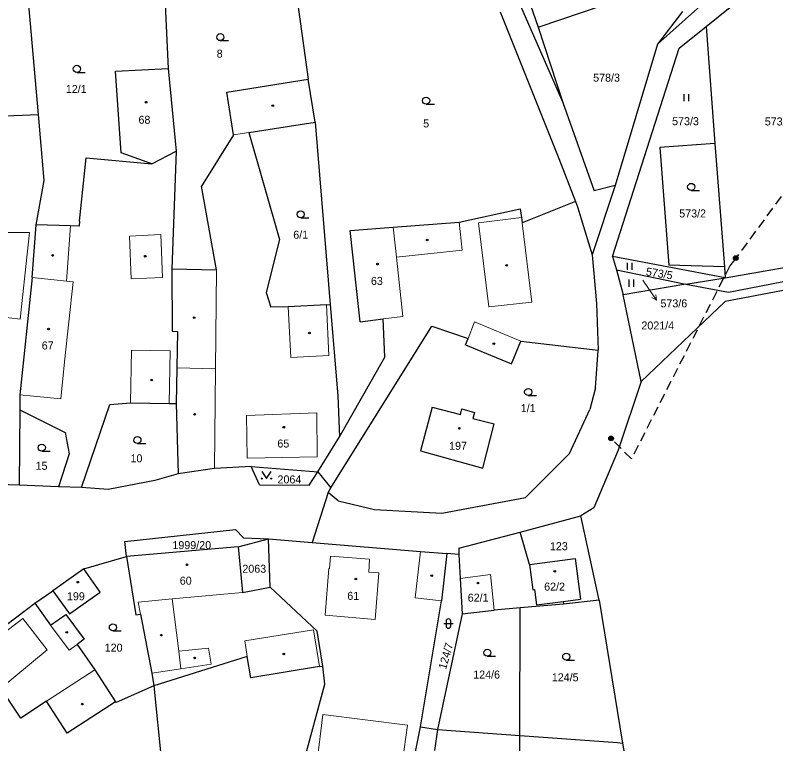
# Model space of a CAD drawing. Extents: x -820420 to -815896, y -1105820 to -1103643.
# Drawn here: x -817534.2 to -817372.7, y -1104713.1 to -1104558.3 of the extents above; entities that cross this region are included whole.
import ezdxf
from ezdxf.enums import TextEntityAlignment as Align

# ---------------------------------------------------------------- set-up
doc = ezdxf.new("R2010")
doc.units = 0
doc.header["$LTSCALE"] = 0.68
doc.linetypes.add('MEDIUM_DASHED', pattern=[4.5, 3, -1.5])
for name, color, linetype, lineweight in [('1', 7, 'Continuous', 25), ('3', 7, 'Continuous', 25), ('4', 7, 'Continuous', 13), ('5', 7, 'Continuous', 25), ('6', 7, 'Continuous', 25), ('7', 7, 'Continuous', 13)]:
    doc.layers.add(name, color=color, linetype=linetype, lineweight=lineweight)
doc.layers.add('2', color=7, linetype='Continuous')

msp = doc.modelspace()

# ---------------------------------------------------------------- linework, layer by layer
at = {"layer": '1'}
for p, q in [((-817441.18, -1104523.68), (-817417.92, -1104576.87)), ((-817502.73, -1104548.77), (-817501.77, -1104569.64)), ((-817475.12, -1104549.37), (-817472.04, -1104571.95)), ((-817423.18, -1104560.9), (-817391.37, -1104550.02)), ((-817529.32, -1104579.44), (-817531.74, -1104551.54)), ((-817426.48, -1104551.26), (-817423.18, -1104560.9)), ((-817397.84, -1104564.5), (-817382.77, -1104550.99)), ((-817387.52, -1104560.73), (-817379.33, -1104554.1)), ((-817431.25, -1104557.62), (-817418.76, -1104588.74)), ((-817392.52, -1104557.51), (-817397.84, -1104564.5)), ((-817423.18, -1104560.9), (-817417.92, -1104576.87)), ((-817393.24, -1104565.36), (-817387.52, -1104560.73)), ((-817387.52, -1104560.73), (-817385.62, -1104585.58)), ((-817397.84, -1104564.5), (-817406.82, -1104594.49)), ((-817407.42, -1104609.58), (-817393.24, -1104565.36)), ((-817512.93, -1104570.24), (-817501.77, -1104569.64)), ((-817501.77, -1104569.64), (-817500.07, -1104587.25)), ((-817511.77, -1104587.6), (-817512.93, -1104570.24)), ((-817489.29, -1104574.65), (-817472.04, -1104571.95)), ((-817470.51, -1104581.09), (-817472.04, -1104571.95)), ((-817487.91, -1104583.78), (-817489.29, -1104574.65)), ((-817417.92, -1104576.87), (-817411.31, -1104595.61)), ((-817549.95, -1104580.27), (-817529.32, -1104579.44)), ((-817528.1, -1104593.46), (-817529.32, -1104579.44)), ((-817484.66, -1104583.28), (-817470.51, -1104581.09)), ((-817470.51, -1104581.09), (-817467.34, -1104619.81)), ((-817487.91, -1104583.78), (-817494.65, -1104594.66)), ((-817484.66, -1104583.28), (-817478.11, -1104605.95)), ((-817385.62, -1104585.58), (-817397.32, -1104586.47)), ((-817385.62, -1104585.58), (-817383.62, -1104611.82)), ((-817505.24, -1104589.89), (-817511.77, -1104587.6)), ((-817505.24, -1104589.89), (-817500.07, -1104587.25)), ((-817500.07, -1104587.25), (-817500.99, -1104612.19)), ((-817397.32, -1104586.47), (-817395.42, -1104611.47)), ((-817520.58, -1104602.07), (-817519.18, -1104588.65)), ((-817519.18, -1104588.65), (-817505.24, -1104589.89)), ((-817418.76, -1104588.74), (-817415.22, -1104597.92)), ((-817529.8, -1104602.87), (-817528.1, -1104593.46)), ((-817491.49, -1104612.43), (-817494.65, -1104594.66)), ((-817406.82, -1104594.49), (-817411.74, -1104609.27)), ((-817406.82, -1104594.49), (-817411.31, -1104595.61)), ((-817415.22, -1104597.92), (-817426.54, -1104602.45)), ((-817415.22, -1104597.92), (-817414.8, -1104599.04)), ((-817414.8, -1104599.04), (-817411.74, -1104609.27)), ((-817439.94, -1104602.31), (-817426.97, -1104599.46)), ((-817426.97, -1104599.46), (-817426.69, -1104601.3)), ((-817520.58, -1104602.07), (-817520.69, -1104603.15)), ((-817453.96, -1104603.38), (-817439.94, -1104602.31)), ((-817426.69, -1104601.3), (-817426.54, -1104602.45)), ((-817530.64, -1104614.06), (-817529.8, -1104602.87)), ((-817522.52, -1104603.09), (-817529.8, -1104602.87)), ((-817520.69, -1104603.15), (-817522.52, -1104603.09)), ((-817463.07, -1104604.07), (-817453.96, -1104603.38)), ((-817461.01, -1104623.45), (-817463.07, -1104604.07)), ((-817478.11, -1104605.95), (-817480.92, -1104617.24)), ((-817383.44, -1104614.12), (-817352.01, -1104608.6)), ((-817411.74, -1104609.27), (-817410.77, -1104619.61)), ((-817383.44, -1104614.12), (-817407.42, -1104609.58)), ((-817383.62, -1104611.82), (-817395.42, -1104611.47)), ((-817383.62, -1104611.82), (-817383.44, -1104614.12)), ((-817382.75, -1104617.18), (-817351.68, -1104611.19)), ((-817500.99, -1104612.19), (-817500.9, -1104625.43)), ((-817500.99, -1104612.19), (-817491.49, -1104612.43)), ((-817406.55, -1104612.43), (-817391.79, -1104615.47)), ((-817351.25, -1104613.05), (-817383.47, -1104619.16)), ((-817530.64, -1104614.06), (-817533.25, -1104639.01)), ((-817391.79, -1104615.47), (-817383.44, -1104614.12)), ((-817391.79, -1104615.47), (-817405.13, -1104617.71)), ((-817391.79, -1104615.47), (-817382.75, -1104617.18)), ((-817480.92, -1104617.24), (-817479.98, -1104620.37)), ((-817401.27, -1104636.18), (-817405.13, -1104617.71)), ((-817468.15, -1104619.86), (-817476.24, -1104620.27)), ((-817468.15, -1104619.86), (-817467.34, -1104619.81)), ((-817467.34, -1104619.81), (-817465.75, -1104639.18)), ((-817410.77, -1104619.61), (-817410.43, -1104629.49)), ((-817383.47, -1104619.16), (-817401.27, -1104636.18)), ((-817476.24, -1104620.27), (-817479.98, -1104620.37)), ((-817461.01, -1104623.45), (-817456.08, -1104622.84)), ((-817455.74, -1104630.98), (-817456.08, -1104622.84)), ((-817467.19, -1104658.73), (-817445.78, -1104624.37)), ((-817445.78, -1104624.37), (-817438.05, -1104627.03)), ((-817500.9, -1104625.43), (-817499.77, -1104625.53)), ((-817499.77, -1104625.53), (-817499.91, -1104633.28)), ((-817438.58, -1104628.39), (-817438.05, -1104627.03)), ((-817428.81, -1104632.43), (-817426.85, -1104627.58)), ((-817426.85, -1104627.58), (-817410.43, -1104629.49)), ((-817438.58, -1104628.39), (-817428.81, -1104632.43)), ((-817411.02, -1104637.48), (-817410.43, -1104629.49)), ((-817465.4, -1104647.88), (-817455.74, -1104630.98)), ((-817499.91, -1104633.28), (-817500.05, -1104640.8)), ((-817401.27, -1104636.18), (-817406.17, -1104650.76)), ((-817411.02, -1104637.48), (-817412.18, -1104642.11)), ((-817533.25, -1104639.01), (-817533.28, -1104642.16)), ((-817465.75, -1104639.18), (-817465.4, -1104647.88)), ((-817520.18, -1104658.67), (-817514.17, -1104641.02)), ((-817514.17, -1104641.02), (-817509.75, -1104640.7)), ((-817509.75, -1104640.7), (-817501.55, -1104640.81)), ((-817501.55, -1104640.81), (-817500.05, -1104640.8)), ((-817500.05, -1104640.8), (-817499.62, -1104655.74)), ((-817533.28, -1104642.16), (-817533.4, -1104658.16)), ((-817533.28, -1104642.16), (-817523.63, -1104646.99)), ((-817445.68, -1104641.62), (-817448.13, -1104650.89)), ((-817445.68, -1104641.62), (-817439.69, -1104643.2)), ((-817439.69, -1104643.2), (-817439.36, -1104641.94)), ((-817439.36, -1104641.94), (-817436.73, -1104642.75)), ((-817436.73, -1104642.75), (-817437.05, -1104644.03)), ((-817416.53, -1104651.45), (-817412.18, -1104642.11)), ((-817437.05, -1104644.03), (-817432.54, -1104645.18)), ((-817434.95, -1104654.6), (-817432.54, -1104645.18)), ((-817523.63, -1104646.99), (-817522.78, -1104651.49)), ((-817469.96, -1104655.35), (-817465.4, -1104647.88)), ((-817448.13, -1104650.89), (-817434.95, -1104654.6)), ((-817406.17, -1104650.76), (-817411.32, -1104662.96)), ((-817522.78, -1104651.49), (-817525.03, -1104658.56)), ((-817425.83, -1104660.79), (-817416.53, -1104651.45)), ((-817499.62, -1104655.74), (-817504.59, -1104657.17)), ((-817491.9, -1104654.63), (-817499.62, -1104655.74)), ((-817484.15, -1104654.2), (-817491.9, -1104654.63)), ((-817484.15, -1104654.2), (-817469.96, -1104655.35)), ((-817482.35, -1104658.14), (-817484.15, -1104654.2)), ((-817471.82, -1104658.18), (-817469.96, -1104655.35)), ((-817469.96, -1104655.35), (-817467.19, -1104658.73)), ((-817504.59, -1104657.17), (-817514.48, -1104659.13)), ((-817533.4, -1104658.16), (-817540.36, -1104657.93)), ((-817525.03, -1104658.56), (-817533.4, -1104658.16)), ((-817520.18, -1104658.67), (-817525.03, -1104658.56)), ((-817514.48, -1104659.13), (-817520.18, -1104658.67)), ((-817482.35, -1104658.14), (-817471.82, -1104658.18)), ((-817467.8, -1104659.72), (-817467.19, -1104658.73)), ((-817467.8, -1104659.72), (-817471.18, -1104670.36)), ((-817465.66, -1104661.53), (-817467.8, -1104659.72)), ((-817465.66, -1104661.53), (-817457.93, -1104663.36)), ((-817443.6, -1104664.13), (-817425.83, -1104660.79)), ((-817457.93, -1104663.36), (-817443.6, -1104664.13)), ((-817411.32, -1104662.96), (-817414.13, -1104664.73)), ((-817426.97, -1104668.14), (-817414.13, -1104664.73)), ((-817410.25, -1104682.64), (-817414.13, -1104664.73)), ((-817510.93, -1104670.14), (-817487.47, -1104667.61)), ((-817487.47, -1104667.61), (-817485.77, -1104669.36)), ((-817440.04, -1104671.55), (-817426.97, -1104668.14)), ((-817425.03, -1104675.01), (-817426.97, -1104668.14)), ((-817510.59, -1104673.34), (-817510.93, -1104670.14)), ((-817486.89, -1104671.29), (-817480.45, -1104669.56)), ((-817485.77, -1104669.36), (-817480.45, -1104669.56)), ((-817480.06, -1104679.83), (-817480.45, -1104669.56)), ((-817480.45, -1104669.56), (-817471.18, -1104670.36)), ((-817486.89, -1104671.29), (-817510.59, -1104673.34)), ((-817486.89, -1104671.29), (-817486.27, -1104677.91)), ((-817471.18, -1104670.36), (-817448.16, -1104672.27)), ((-817440.04, -1104671.55), (-817439.99, -1104672.94)), ((-817519.66, -1104675.99), (-817510.59, -1104673.34)), ((-817510.59, -1104673.34), (-817508.6, -1104685.74)), ((-817448.16, -1104672.27), (-817442.59, -1104672.69)), ((-817442.59, -1104672.69), (-817443.7, -1104682.77)), ((-817439.99, -1104672.94), (-817442.59, -1104672.69)), ((-817439.99, -1104672.94), (-817439.74, -1104678.02)), ((-817425.03, -1104675.01), (-817415.32, -1104673.77)), ((-817425.03, -1104675.01), (-817424.33, -1104680.42)), ((-817415.32, -1104673.77), (-817414.21, -1104682.42)), ((-817519.66, -1104675.99), (-817526.22, -1104680.64)), ((-817516.18, -1104680.91), (-817519.66, -1104675.99)), ((-817486.27, -1104677.91), (-817485.99, -1104680.95)), ((-817439.74, -1104678.02), (-817439.3, -1104685.53)), ((-817485.99, -1104680.95), (-817480.06, -1104679.83)), ((-817480.06, -1104679.83), (-817470.1, -1104689.17)), ((-817530.1, -1104683.23), (-817526.22, -1104680.64)), ((-817526.22, -1104680.64), (-817522.72, -1104685.55)), ((-817522.72, -1104685.55), (-817516.18, -1104680.91)), ((-817424.33, -1104680.42), (-817423.93, -1104680.37)), ((-817423.93, -1104680.37), (-817423.51, -1104683.62)), ((-817448.17, -1104709.55), (-817443.7, -1104682.77)), ((-817423.51, -1104683.62), (-817417.86, -1104682.89)), ((-817417.86, -1104682.89), (-817414.21, -1104682.42)), ((-817417.86, -1104682.89), (-817417.8, -1104683.46)), ((-817410.25, -1104682.64), (-817417.8, -1104683.46)), ((-817410.25, -1104682.64), (-817405.25, -1104712.96)), ((-817538.53, -1104689.62), (-817530.1, -1104683.23)), ((-817530.1, -1104683.23), (-817526.76, -1104687.93)), ((-817439.3, -1104685.53), (-817432.5, -1104684.76)), ((-817426.99, -1104684.27), (-817432.5, -1104684.76)), ((-817427.05, -1104711.34), (-817426.99, -1104684.27)), ((-817417.8, -1104683.46), (-817426.99, -1104684.27)), ((-817526.76, -1104687.93), (-817523.51, -1104685.66)), ((-817523.51, -1104685.66), (-817519.58, -1104690.88)), ((-817508.6, -1104685.74), (-817507.66, -1104685.6)), ((-817507.66, -1104685.6), (-817505.24, -1104698.12)), ((-817439.3, -1104685.53), (-817444.53, -1104710.06)), ((-817468.92, -1104696.62), (-817470.1, -1104689.17)), ((-817519.58, -1104690.88), (-817521.08, -1104692.02)), ((-817521.08, -1104692.02), (-817517.33, -1104697.42)), ((-817484.96, -1104694.6), (-817504.8, -1104700.81)), ((-817484.22, -1104699.11), (-817484.96, -1104694.6)), ((-817517.33, -1104697.42), (-817512.91, -1104704.21)), ((-817469.61, -1104696.73), (-817484.22, -1104699.11)), ((-817469.61, -1104696.73), (-817468.92, -1104696.62)), ((-817468.5, -1104700.47), (-817468.92, -1104696.62)), ((-817505.24, -1104698.12), (-817504.8, -1104700.81)), ((-817504.8, -1104700.81), (-817512.8, -1104704.38)), ((-817504.8, -1104700.81), (-817500.74, -1104740.44)), ((-817472.89, -1104716.68), (-817468.5, -1104700.47)), ((-817533.07, -1104707.69), (-817536.14, -1104703)), ((-817527.59, -1104704.1), (-817533.07, -1104707.69)), ((-817523.18, -1104710.89), (-817527.59, -1104704.1)), ((-817512.91, -1104704.21), (-817523.18, -1104710.89)), ((-817512.91, -1104704.21), (-817512.8, -1104704.38)), ((-817450.14, -1104719.46), (-817448.17, -1104709.55)), ((-817448.17, -1104709.55), (-817444.53, -1104710.06)), ((-817444.53, -1104710.06), (-817445.18, -1104714.52)), ((-817444.53, -1104710.06), (-817427.05, -1104711.34)), ((-817427.12, -1104719.23), (-817427.05, -1104711.34)), ((-817427.05, -1104711.34), (-817406.31, -1104712.85)), ((-817406.31, -1104712.85), (-817405.25, -1104712.96)), ((-817405.25, -1104712.96), (-817404.87, -1104715.4))]:
    msp.add_line(p, q, dxfattribs=at)
msp.add_lwpolyline([(-817407.42, -1104609.58), (-817406.55, -1104612.43), (-817405.13, -1104617.71)], dxfattribs=at)
at = {"layer": '3'}
for p, q in [((-817490.693, -1104563.73), (-817488.943, -1104563.73)), ((-817521.153, -1104570.48), (-817519.403, -1104570.48)), ((-817392.191, -1104576.6), (-817392.191, -1104575.1)), ((-817391.19, -1104576.6), (-817391.19, -1104575.1)), ((-817446.963, -1104577.23), (-817445.213, -1104577.23)), ((-817390.673, -1104595.56), (-817388.923, -1104595.56)), ((-817473.613, -1104601.39), (-817471.863, -1104601.39)), ((-817404.211, -1104612.41), (-817404.211, -1104610.91)), ((-817403.21, -1104612.41), (-817403.21, -1104610.91)), ((-817403.881, -1104616.01), (-817403.881, -1104614.51)), ((-817402.88, -1104616.01), (-817402.88, -1104614.51)), ((-817425.293, -1104639.14), (-817423.543, -1104639.14)), ((-817508.283, -1104649.35), (-817506.533, -1104649.35)), ((-817528.593, -1104650.96), (-817526.843, -1104650.96)), ((-817443.221, -1104687.591), (-817441.219, -1104687.591)), ((-817442.721, -1104687.091), (-817442.721, -1104688.092)), ((-817441.719, -1104688.092), (-817441.719, -1104687.091)), ((-817513.503, -1104689.14), (-817511.753, -1104689.14)), ((-817433.983, -1104694.53), (-817432.233, -1104694.53)), ((-817417.213, -1104695.36), (-817415.463, -1104695.36))]:
    msp.add_line(p, q, dxfattribs=at)
msp.add_lwpolyline([(-817481.89, -1104655.269), (-817480.89, -1104656.77), (-817479.89, -1104655.269)], dxfattribs=at)
for centre, radius in [((-817490.6929, -1104562.9798), 0.75), ((-817521.1529, -1104569.7298), 0.75), ((-817446.9629, -1104576.4798), 0.75), ((-817390.6729, -1104594.8098), 0.75), ((-817473.6129, -1104600.6398), 0.75), ((-817425.2929, -1104638.3898), 0.75), ((-817508.2829, -1104648.5998), 0.75), ((-817528.5929, -1104650.2098), 0.75), ((-817481.89, -1104656.7695), 0.1), ((-817479.89, -1104656.7695), 0.1), ((-817513.5029, -1104688.3898), 0.75), ((-817433.9829, -1104693.7798), 0.75), ((-817417.2129, -1104694.6098), 0.75)]:
    msp.add_circle(centre, radius, dxfattribs=at)
for centre, start, end in [((-817442.22, -1104687.0909), 0, 180), ((-817442.22, -1104688.0909), 180, 359.98789)]:
    msp.add_arc(centre, 0.5, start, end, dxfattribs=at)
at = {"layer": '4'}
for p, q in [((-817487.91, -1104583.78), (-817484.66, -1104583.28)), ((-817439.29, -1104608.24), (-817439.94, -1104602.31)), ((-817435.83, -1104602.42), (-817426.69, -1104601.3)), ((-817433.65, -1104620.26), (-817435.83, -1104602.42)), ((-817523.37, -1104614.82), (-817522.52, -1104603.09)), ((-817453.26, -1104609.76), (-817453.96, -1104603.38)), ((-817426.54, -1104602.45), (-817424.49, -1104619.29)), ((-817538.57, -1104604.48), (-817531.2, -1104604.49)), ((-817531.2, -1104604.49), (-817533.18, -1104622.89)), ((-817503.3, -1104604.95), (-817509.94, -1104605.25)), ((-817509.94, -1104605.25), (-817509.6, -1104614.32)), ((-817502.96, -1104614.07), (-817503.3, -1104604.95)), ((-817453.26, -1104609.76), (-817439.29, -1104608.24)), ((-817451.89, -1104622.34), (-817453.26, -1104609.76)), ((-817523.37, -1104614.82), (-817530.64, -1104614.06)), ((-817523.79, -1104632), (-817521.93, -1104614.97)), ((-817521.93, -1104614.97), (-817523.37, -1104614.82)), ((-817509.6, -1104614.32), (-817502.96, -1104614.07)), ((-817468.15, -1104619.86), (-817467.61, -1104630.62)), ((-817424.49, -1104619.29), (-817433.65, -1104620.26)), ((-817475.7, -1104631.03), (-817476.24, -1104620.27)), ((-817540.5, -1104622.09), (-817533.18, -1104622.89)), ((-817456.08, -1104622.84), (-817451.89, -1104622.34)), ((-817436.7, -1104623.51), (-817438.05, -1104627.03)), ((-817436.7, -1104623.51), (-817426.85, -1104627.58)), ((-817509.54, -1104629.48), (-817509.75, -1104640.7)), ((-817467.61, -1104630.62), (-817475.7, -1104631.03)), ((-817524.53, -1104639.86), (-817523.79, -1104632)), ((-817491.69, -1104633.46), (-817491.9, -1104654.63)), ((-817533.25, -1104639.01), (-817524.53, -1104639.86)), ((-817485.12, -1104643.41), (-817470.21, -1104642.79)), ((-817484.96, -1104652.43), (-817485.12, -1104643.41)), ((-817467.26, -1104673.26), (-817467.5, -1104675.9)), ((-817459.01, -1104673.88), (-817467.26, -1104673.26)), ((-817448.16, -1104672.27), (-817449.28, -1104682.14)), ((-817459.16, -1104676.64), (-817459.01, -1104673.88)), ((-817467.63, -1104675.89), (-817468.43, -1104685.8)), ((-817467.5, -1104675.9), (-817467.63, -1104675.89)), ((-817459.16, -1104676.64), (-817457.02, -1104676.8)), ((-817457.78, -1104686.69), (-817457.02, -1104676.8)), ((-817439.74, -1104678.02), (-817433.32, -1104677.17)), ((-817433.32, -1104677.17), (-817432.5, -1104684.76)), ((-817485.99, -1104680.95), (-817500.93, -1104682.34)), ((-817500.93, -1104682.34), (-817508.16, -1104683.01)), ((-817508.16, -1104683.01), (-817507.66, -1104685.6)), ((-817500.93, -1104682.34), (-817499.52, -1104693.48)), ((-817449.28, -1104682.14), (-817443.7, -1104682.77)), ((-817468.43, -1104685.8), (-817457.78, -1104686.69)), ((-817537.86, -1104690.48), (-817532.62, -1104686.49)), ((-817532.62, -1104686.49), (-817527.44, -1104693.13)), ((-817526.76, -1104687.93), (-817522.78, -1104693.26)), ((-817470.89, -1104688.89), (-817485.5, -1104691.27)), ((-817470.89, -1104688.89), (-817469.61, -1104696.73)), ((-817485.5, -1104691.27), (-817484.96, -1104694.6)), ((-817522.78, -1104693.26), (-817521.08, -1104692.02)), ((-817527.44, -1104693.13), (-817544.22, -1104707.05)), ((-817499.52, -1104693.48), (-817499.05, -1104697.2)), ((-817517.33, -1104697.42), (-817527.59, -1104704.1)), ((-817505.24, -1104698.12), (-817499.05, -1104697.2)), ((-817499.05, -1104697.2), (-817492.62, -1104696.24)), ((-817468.91, -1104706.9), (-817470.14, -1104717.01)), ((-817450.96, -1104709.14), (-817468.91, -1104706.9)), ((-817452.34, -1104719.17), (-817450.96, -1104709.14))]:
    msp.add_line(p, q, dxfattribs=at)
for points in [[(-817491.49, -1104612.43), (-817491.69, -1104633.46), (-817499.91, -1104633.28)], [(-817501.55, -1104640.81), (-817501.34, -1104629.63), (-817509.54, -1104629.48)], [(-817470.21, -1104642.79), (-817470.11, -1104652.17), (-817484.96, -1104652.43)], [(-817492.62, -1104696.24), (-817493.2, -1104692.82), (-817499.52, -1104693.48)]]:
    msp.add_lwpolyline(points, dxfattribs=at)
at = {"layer": '5'}
for centre in [(-817506.4368, -1104576.8192), (-817479.5368, -1104577.5592), (-817446.7468, -1104606.0892), (-817526.2768, -1104609.3692), (-817506.6268, -1104609.5292), (-817457.2968, -1104611.2192), (-817429.8468, -1104611.4692), (-817496.2368, -1104622.5992), (-817527.1668, -1104624.9892), (-817471.7568, -1104625.8592), (-817432.5768, -1104628.1092), (-817505.2468, -1104635.8392), (-817496.1368, -1104643.1392), (-817477.1968, -1104645.8592), (-817439.9068, -1104646.0892), (-817497.7468, -1104675.0992), (-817419.6468, -1104676.4792), (-817461.9168, -1104678.1192), (-817445.7668, -1104677.3992), (-817520.9568, -1104678.7792), (-817435.9568, -1104678.9792), (-817523.2968, -1104689.4492), (-817503.2168, -1104690.0492), (-817477.1968, -1104694.0592), (-817496.1368, -1104694.8992), (-817519.9868, -1104704.6992)]:
    msp.add_circle(centre, 0.175, dxfattribs=at)
at = {"layer": '6', "linetype": 'MEDIUM_DASHED'}
for p, q in [((-817344.36, -1104559.87), (-817381.2, -1104609.95)), ((-817381.2, -1104609.95), (-817382.46, -1104611.6)), ((-817382.46, -1104611.6), (-817403.38, -1104652.59)), ((-817403.38, -1104652.59), (-817407.69, -1104648.26))]:
    msp.add_line(p, q, dxfattribs=at)
at = {"layer": '6'}
for centre, radius in [((-817381.2034, -1104609.9499), 0.5), ((-817381.2034, -1104609.9499), 0.4), ((-817381.2034, -1104609.9499), 0.3), ((-817381.2034, -1104609.9499), 0.2), ((-817381.2034, -1104609.9499), 0.1), ((-817407.6934, -1104648.2599), 0.5), ((-817407.6934, -1104648.2599), 0.4), ((-817407.6934, -1104648.2599), 0.3), ((-817407.6934, -1104648.2599), 0.2), ((-817407.6934, -1104648.2599), 0.1)]:
    msp.add_circle(centre, radius, dxfattribs=at)
at = {"layer": '7'}
msp.add_line((-817398.072, -1104618.848), (-817398.217, -1104617.738), dxfattribs=at)
msp.add_lwpolyline([(-817400.92, -1104614.62), (-817399.75, -1104616.36), (-817398.072, -1104618.848), (-817399.047, -1104618.298)], dxfattribs=at)

# ---------------------------------------------------------------- texts
at = {"layer": '2'}
for s, p in [('8', (-817490.82, -1104567.345)), ('578/3', (-817408.65, -1104572.445)), ('12/1', (-817521.279, -1104574.855)), ('68', (-817506.799, -1104581.395)), ('5', (-817446.97, -1104582.175)), ('573/3', (-817391.88, -1104581.695)), ('573/1', (-817372.2, -1104581.755)), ('573/2', (-817390.37, -1104601.295)), ('6/1', (-817473.61, -1104605.815)), ('63', (-817457.429, -1104615.635)), ('2021/4', (-817397.77, -1104625.105)), ('67', (-817527.349, -1104629.355)), ('1/1', (-817425.3, -1104642.655)), ('65', (-817477.299, -1104650.185)), ('197', (-817440.189, -1104650.665)), ('10', (-817508.499, -1104653.325)), ('15', (-817528.659, -1104654.915)), ('2064', (-817476.01, -1104657.805)), ('1999/20', (-817496.749, -1104671.765)), ('123', (-817418.789, -1104671.995)), ('2063', (-817483.47, -1104676.785)), ('60', (-817498.029, -1104679.325)), ('62/2', (-817419.689, -1104680.585)), ('199', (-817521.359, -1104682.635)), ('61', (-817462.449, -1104682.545)), ('62/1', (-817435.919, -1104682.935)), ('120', (-817513.339, -1104693.555)), ('124/6', (-817434.12, -1104699.275)), ('124/5', (-817417.43, -1104699.855))]:
    msp.add_text(s, height=1.7, dxfattribs=at).set_placement(p, align=Align.CENTER)
for s, rotation, p in [('573/5', 351, (-817397.568, -1104614.0304)), ('124/7', 74, (-817441.9771, -1104694.7078))]:
    msp.add_text(s, height=1.7, rotation=rotation, dxfattribs=at).set_placement(p, align=Align.CENTER)
msp.add_text('573/6', height=1.7, dxfattribs=at).set_placement((-817397.2, -1104620.405))

doc.saveas('drawing.dxf')
